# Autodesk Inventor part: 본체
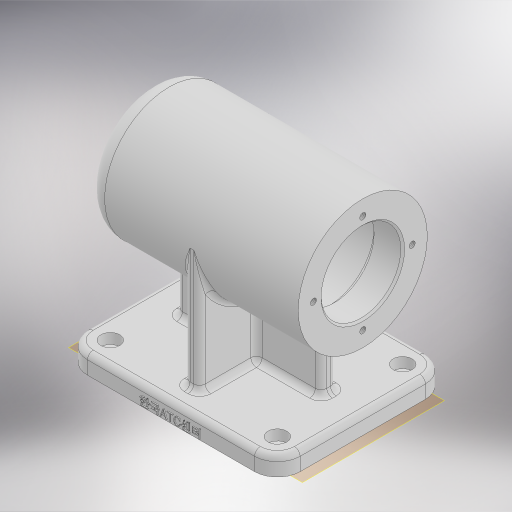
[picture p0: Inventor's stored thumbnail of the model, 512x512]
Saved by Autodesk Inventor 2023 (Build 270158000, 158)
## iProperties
Created: 2026-08
Part Number: 본체
Material: 일반
Document SubType Name: Modeling
Designer: home
Density: 1 g/cm^3
Appearance: 기본값
Author: home
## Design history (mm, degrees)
sketch "스케치5"
  geometry: C1 r 34 at (0, 0); 1 further point
  constraints: 1 centre point, 1 coincident
  dimensions: "d28" = 68 diameter of C1
extrude "돌출1" new body sketch "스케치5" stored distance "d29" = 112; taper "d30" = 0 deg
sketch "스케치6"
  geometry: C1 r 21 at (0, 0); 1 further point
  constraints: 1 centre point, 1 coincident
  dimensions: "d31" = 42 diameter of C1
extrude "돌출2" cut sketch "스케치6" distance "d32" = 15; taper "d33" = 0 deg
sketch "스케치7"
  geometry: C1 r 24 at (0, 0); 1 further point
  constraints: 1 centre point, 1 coincident
  dimensions: "d34" = 48 diameter of C1
extrude "돌출3" cut sketch "스케치7" distance "d35" = 54; taper "d36" = 0 deg
sketch "스케치8"
  geometry: C1 r 21 at (0, 0); 1 further point
  constraints: 1 centre point, 1 coincident
  dimensions: "d37" = 42 diameter of C1
extrude "돌출4" cut sketch "스케치8" distance "d38" = 12; taper "d39" = 0 deg
sketch "스케치9"
  geometry: C1 r 17.5 at (0, 0); 1 further point
  constraints: 1 centre point, 1 coincident
  dimensions: "d40" = 35 diameter of C1
extrude "돌출5" cut sketch "스케치9" distance "d41" = 18; taper "d42" = 0 deg
sketch "스케치10"
  geometry: C1 r 16 at (0, 0); 1 further point
  constraints: 1 centre point, 1 coincident
  dimensions: "d43" = 32 diameter of C1
extrude "돌출6" cut sketch "스케치10" distance "d44" = 4; taper "d45" = 0 deg
sketch "스케치11"
  geometry: C1 r 10.5 at (0, 0); 1 further point
  constraints: 1 centre point, 1 coincident
  dimensions: "d46" = 21 diameter of C1
extrude "돌출7" cut sketch "스케치11" distance "d47" = 3; taper "d48" = 0 deg
fillet "모깎기1" dims "d49" = 3
fillet "모깎기2" dims "d50" = 0.6
fillet "모깎기3" dims "d51" = 0.6
fillet "모깎기4" dims "d52" = 3
fillet "모깎기5" dims "d53" = 3
chamfer "모따기1" distance "d54" = 1; stored, may be unused: second distance "d55" = 2, angle "d56" = 45 deg
fillet "모깎기6" dims "d57" = 10
sketch "스케치12"
  geometry: 2 further points
  constraints: 1 vertical alignment
  dimensions: "d65" = 26 distance of point (0, 0) point (0, 26)
hole "구멍1" sketch "스케치12" at (0, 26) diameter "d58" = 3.242; stored, may be unused: countersink angle "d62" = 90 deg, drill point angle "d64" = 118 deg; dims "d59" = 8, "d60" = 4, "d61" = 2, "d63" = 10
node "작업 평면1"
sketch "스케치13"
  geometry: L1 (56, -45)-(-56, -45); L2 (-56, -45)-(-56, 45); L3 (-56, 45)-(56, 45); L4 (56, 45)-(56, -45); 3 further points
  constraints: 8 end point, 2 midpoint, 2 parallel, 1 horizontal, 1 horizontal alignment, 1 perpendicular, 1 vertical alignment
  dimensions: "d70" = 90 distance of L1.end L2.end; "d71" = 112 distance of L2.end L3.end
extrude "돌출8" join sketch "스케치13" distance "d72" = 10; taper "d73" = 0 deg
fillet "모깎기7" dims "d74" = 12
sketch "스케치14"
  geometry: A1 r 12 centre (44, -33) between (44, -45) and (56, -33) reference; A2 r 12 centre (44, 33) between (56, 33) and (44, 45) reference; A3 r 12 centre (-44, -33) between (-56, -33) and (-44, -45) reference; A4 r 12 centre (-44, 33) between (-44, 45) and (-56, 33) reference; 5 further points
  constraints: 4 coincident
hole "구멍2" sketch "스케치14" at (44, -33), (44, 33), (-44, -33), (-44, 33) diameter "d75" = 5.5; stored, may be unused: countersink angle "d79" = 90 deg, drill point angle "d81" = 0 deg; dims "d76" = 8, "d77" = 10, "d78" = 5.5, "d80" = 10
sketch "스케치15"
  geometry: L1 (-38, 4)-(38, 4); L2 (38, 4)-(38, -4); L3 (38, -4)-(-38, -4); L4 (-38, -4)-(-38, 4); L5 (-4, 34)-(4, 34); L6 (4, 34)-(4, -34); L7 (4, -34)-(-4, -34); L8 (-4, -34)-(-4, 34); C1 r 2.75 at (44, 33) reference; C2 r 2.75 at (44, -33) reference; 9 further points
  constraints: 16 end point, 4 midpoint, 4 parallel, 2 horizontal, 2 horizontal alignment, 2 perpendicular, 2 vertical alignment
  dimensions: "d82" = 8 distance between parallel lines of L3 L1; "d83" = 76 distance of L1.start L1.end; "d84" = 68 distance of L7.end L5.start; "d85" = 8 distance of L5.start L5.end
extrude "돌출9" join sketch "스케치15" stored distance "d86" = 10; taper "d87" = 0 deg
fillet "모깎기8" dims "d88" = 3
sketch "스케치16"
  geometry: L1 (0, 0)-(88, 0) reference; 2 further points
  constraints: 1 vertical alignment, 1 other
  dimensions: "d89" = 3 distance from line of L1 point (44, 3)
fillet "모깎기9" dims "d90" = 3
fillet "모깎기10" dims "d91" = 3
fillet "모깎기11" dims "d92" = 3
fillet "모깎기12" dims "d93" = 3
feature "엠보싱1" dims "d94" = 0.5, "d95" = 0
feature "ͼ耀;耀΀耀΂耀΄耀Ά耀Έ耀Ί耀" dims "d28" = 68, "d29" = 112, "d30" = 0, "d31" = 42, "d32" = 15, "d33" = 0, "d34" = 48, "d35" = 54, "d36" = 0, "d37" = 42, "d38" = 12, "d39" = 0, "d40" = 35, "d41" = 18, "d42" = 0, "d43" = 32, "d44" = 4, "d45" = 0, "d46" = 21, "d47" = 3, "d48" = 0, "d49" = 3, "d50" = 0.6, "d51" = 0.6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
node "솔리드1"
pattern_circular "원형 패턴1" dims angle "d67" = 360 deg
feature "A9D066F2-1C7D-4E18-AEED-F7BC21143FA4" dims "d58" = 3.242, "d59" = 8, "d60" = 4, "d61" = 2, "d62" = 90 deg, "d63" = 10, "d64" = 118 deg
